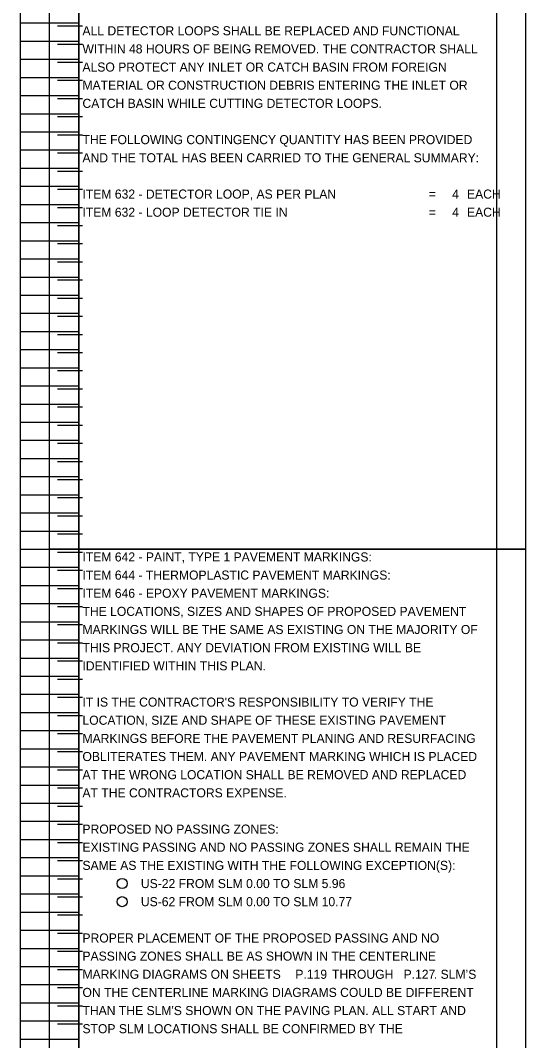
# Model space of a CAD drawing. Extents: x 12522 to 13018, y 1124 to 1902.
# Drawn here: x 12521.92 to 12529.71, y 1701.09 to 1716.83 of the extents above; entities that cross this region are included whole.
import ezdxf

# ---------------------------------------------------------------- set-up
doc = ezdxf.new("R2010")
doc.units = 0
doc.layers.add('SC_Scratch1', color=7, linetype='Continuous')
doc.layers.add('SH_Text', color=7, linetype='Continuous')

msp = doc.modelspace()

# ---------------------------------------------------------------- linework, layer by layer
at = {"layer": 'SC_Scratch1'}
for p, q in [((12521.919, 1708.671), (12521.919, 1728.831)), ((12522.819, 1708.671), (12522.819, 1728.831)), ((12522.819, 1728.831), (12522.819, 1708.671)), ((12521.919, 1716.791), (12522.819, 1716.791)), ((12522.876, 1716.741), (12522.492, 1716.741)), ((12521.919, 1716.511), (12522.819, 1716.511)), ((12522.876, 1716.461), (12522.492, 1716.461)), ((12521.919, 1716.231), (12522.819, 1716.231)), ((12522.876, 1716.181), (12522.492, 1716.181)), ((12521.919, 1715.951), (12522.819, 1715.951)), ((12522.876, 1715.901), (12522.492, 1715.901)), ((12521.919, 1715.671), (12522.819, 1715.671)), ((12522.876, 1715.621), (12522.492, 1715.621)), ((12521.919, 1715.391), (12522.819, 1715.391)), ((12522.876, 1715.341), (12522.492, 1715.341)), ((12521.919, 1715.111), (12522.819, 1715.111)), ((12522.876, 1715.061), (12522.492, 1715.061)), ((12521.919, 1714.831), (12522.819, 1714.831)), ((12522.876, 1714.781), (12522.492, 1714.781)), ((12521.919, 1714.551), (12522.819, 1714.551)), ((12522.876, 1714.501), (12522.492, 1714.501)), ((12521.919, 1714.271), (12522.819, 1714.271)), ((12522.876, 1714.221), (12522.492, 1714.221)), ((12521.919, 1713.991), (12522.819, 1713.991)), ((12522.876, 1713.941), (12522.492, 1713.941)), ((12521.919, 1713.711), (12522.819, 1713.711)), ((12522.876, 1713.661), (12522.492, 1713.661)), ((12521.919, 1713.431), (12522.819, 1713.431)), ((12522.876, 1713.381), (12522.492, 1713.381)), ((12521.919, 1713.151), (12522.819, 1713.151)), ((12522.876, 1713.101), (12522.492, 1713.101)), ((12521.919, 1712.871), (12522.819, 1712.871)), ((12522.876, 1712.821), (12522.492, 1712.821)), ((12521.919, 1712.591), (12522.819, 1712.591)), ((12522.876, 1712.541), (12522.492, 1712.541)), ((12521.919, 1712.311), (12522.819, 1712.311)), ((12522.876, 1712.261), (12522.492, 1712.261)), ((12521.919, 1712.031), (12522.819, 1712.031)), ((12522.876, 1711.981), (12522.492, 1711.981)), ((12521.919, 1711.751), (12522.819, 1711.751)), ((12522.876, 1711.701), (12522.492, 1711.701)), ((12521.919, 1711.471), (12522.819, 1711.471)), ((12522.876, 1711.421), (12522.492, 1711.421)), ((12521.919, 1711.191), (12522.819, 1711.191)), ((12522.876, 1711.141), (12522.492, 1711.141)), ((12521.919, 1710.911), (12522.819, 1710.911)), ((12522.876, 1710.861), (12522.492, 1710.861)), ((12521.919, 1710.631), (12522.819, 1710.631)), ((12522.876, 1710.581), (12522.492, 1710.581)), ((12521.919, 1710.351), (12522.819, 1710.351)), ((12522.876, 1710.301), (12522.492, 1710.301)), ((12521.919, 1710.071), (12522.819, 1710.071)), ((12522.876, 1710.021), (12522.492, 1710.021)), ((12521.919, 1709.791), (12522.819, 1709.791)), ((12522.876, 1709.741), (12522.492, 1709.741)), ((12521.919, 1709.511), (12522.819, 1709.511)), ((12522.876, 1709.461), (12522.492, 1709.461)), ((12521.919, 1709.231), (12522.819, 1709.231)), ((12522.876, 1709.181), (12522.492, 1709.181)), ((12521.919, 1708.951), (12522.819, 1708.951)), ((12522.876, 1708.901), (12522.492, 1708.901)), ((12521.919, 1708.671), (12522.819, 1708.671)), ((12521.919, 1688.511), (12521.919, 1708.671)), ((12521.919, 1708.671), (12522.819, 1708.671)), ((12522.819, 1688.511), (12522.819, 1708.671)), ((12522.819, 1708.671), (12522.819, 1688.511)), ((12522.876, 1708.621), (12522.492, 1708.621)), ((12521.919, 1708.391), (12522.819, 1708.391)), ((12522.876, 1708.341), (12522.492, 1708.341)), ((12521.919, 1708.111), (12522.819, 1708.111)), ((12522.876, 1708.061), (12522.492, 1708.061)), ((12521.919, 1707.831), (12522.819, 1707.831)), ((12522.876, 1707.781), (12522.492, 1707.781)), ((12521.919, 1707.551), (12522.819, 1707.551)), ((12522.876, 1707.501), (12522.492, 1707.501)), ((12521.919, 1707.271), (12522.819, 1707.271)), ((12522.876, 1707.221), (12522.492, 1707.221)), ((12521.919, 1706.991), (12522.819, 1706.991)), ((12522.876, 1706.941), (12522.492, 1706.941)), ((12521.919, 1706.711), (12522.819, 1706.711)), ((12522.876, 1706.661), (12522.492, 1706.661)), ((12521.919, 1706.431), (12522.819, 1706.431)), ((12522.876, 1706.381), (12522.492, 1706.381)), ((12521.919, 1706.151), (12522.819, 1706.151)), ((12522.876, 1706.101), (12522.492, 1706.101)), ((12521.919, 1705.871), (12522.819, 1705.871)), ((12522.876, 1705.821), (12522.492, 1705.821)), ((12521.919, 1705.591), (12522.819, 1705.591)), ((12522.876, 1705.541), (12522.492, 1705.541)), ((12521.919, 1705.311), (12522.819, 1705.311)), ((12522.876, 1705.261), (12522.492, 1705.261)), ((12521.919, 1705.031), (12522.819, 1705.031)), ((12522.876, 1704.981), (12522.492, 1704.981)), ((12521.919, 1704.751), (12522.819, 1704.751)), ((12522.876, 1704.701), (12522.492, 1704.701)), ((12521.919, 1704.471), (12522.819, 1704.471)), ((12522.876, 1704.421), (12522.492, 1704.421)), ((12521.919, 1704.191), (12522.819, 1704.191)), ((12522.876, 1704.141), (12522.492, 1704.141)), ((12521.919, 1703.911), (12522.819, 1703.911)), ((12522.876, 1703.861), (12522.492, 1703.861)), ((12521.919, 1703.631), (12522.819, 1703.631)), ((12522.876, 1703.581), (12522.492, 1703.581)), ((12521.919, 1703.351), (12522.819, 1703.351)), ((12522.876, 1703.301), (12522.492, 1703.301)), ((12521.919, 1703.071), (12522.819, 1703.071)), ((12522.876, 1703.021), (12522.492, 1703.021)), ((12521.919, 1702.791), (12522.819, 1702.791)), ((12522.876, 1702.741), (12522.492, 1702.741)), ((12521.919, 1702.511), (12522.819, 1702.511)), ((12522.876, 1702.461), (12522.492, 1702.461)), ((12521.919, 1702.231), (12522.819, 1702.231)), ((12522.876, 1702.181), (12522.492, 1702.181)), ((12521.919, 1701.951), (12522.819, 1701.951)), ((12522.876, 1701.901), (12522.492, 1701.901)), ((12521.919, 1701.671), (12522.819, 1701.671)), ((12522.876, 1701.621), (12522.492, 1701.621)), ((12521.919, 1701.391), (12522.819, 1701.391)), ((12522.876, 1701.341), (12522.492, 1701.341)), ((12521.919, 1701.111), (12522.819, 1701.111))]:
    msp.add_line(p, q, dxfattribs=at)
for points in [[(12522.369, 1728.831), (12529.709, 1728.831), (12529.709, 1708.671), (12522.369, 1708.671)], [(12522.819, 1728.831), (12529.259, 1728.831), (12529.259, 1708.671), (12522.819, 1708.671)], [(12522.369, 1708.671), (12529.709, 1708.671), (12529.709, 1688.511), (12522.369, 1688.511)], [(12522.819, 1708.671), (12529.259, 1708.671), (12529.259, 1688.511), (12522.819, 1688.511)]]:
    msp.add_lwpolyline(points, close=True, dxfattribs=at)
at = {"layer": 'SH_Text'}
for centre in [(12523.489, 1703.511), (12523.489, 1703.231)]:
    msp.add_circle(centre, 0.0775, dxfattribs=at)

# ---------------------------------------------------------------- texts
for s, p in [('ALL DETECTOR LOOPS SHALL BE REPLACED AND FUNCTIONAL ', (12522.876, 1716.601)), ('WITHIN 48 HOURS OF BEING REMOVED. THE CONTRACTOR SHALL ', (12522.876, 1716.321)), ('ALSO PROTECT ANY INLET OR CATCH BASIN FROM FOREIGN ', (12522.876, 1716.041)), ('MATERIAL OR CONSTRUCTION DEBRIS ENTERING THE INLET OR ', (12522.876, 1715.761)), ('CATCH BASIN WHILE CUTTING DETECTOR LOOPS.', (12522.876, 1715.481)), ('THE FOLLOWING CONTINGENCY QUANTITY HAS BEEN PROVIDED ', (12522.876, 1714.921)), ('AND THE TOTAL HAS BEEN CARRIED TO THE GENERAL SUMMARY:', (12522.876, 1714.641)), ('ITEM 632 - DETECTOR LOOP, AS PER PLAN', (12522.876, 1714.081)), (' =', (12528.164, 1714.081)), ('4', (12528.578, 1714.081)), ('EACH', (12528.806, 1714.081)), ('ITEM 632 - LOOP DETECTOR TIE IN', (12522.876, 1713.801)), (' =', (12528.164, 1713.801)), ('4', (12528.578, 1713.801)), ('EACH', (12528.806, 1713.801)), ('ITEM 642 - PAINT, TYPE 1 PAVEMENT MARKINGS:', (12522.876, 1708.481)), ('ITEM 644 - THERMOPLASTIC PAVEMENT MARKINGS:', (12522.876, 1708.201)), ('ITEM 646 - EPOXY PAVEMENT MARKINGS:', (12522.876, 1707.921)), ('THE LOCATIONS, SIZES AND SHAPES OF PROPOSED PAVEMENT ', (12522.876, 1707.641)), ('MARKINGS WILL BE THE SAME AS EXISTING ON THE MAJORITY OF ', (12522.876, 1707.361)), ('THIS PROJECT. ANY DEVIATION FROM EXISTING WILL BE ', (12522.876, 1707.081)), ('IDENTIFIED WITHIN THIS PLAN. ', (12522.876, 1706.801)), ("IT IS THE CONTRACTOR'S RESPONSIBILITY TO VERIFY THE ", (12522.876, 1706.241)), ('LOCATION, SIZE AND SHAPE OF THESE EXISTING PAVEMENT ', (12522.876, 1705.961)), ('MARKINGS BEFORE THE PAVEMENT PLANING AND RESURFACING ', (12522.876, 1705.681)), ('OBLITERATES THEM. ANY PAVEMENT MARKING WHICH IS PLACED ', (12522.876, 1705.401)), ('AT THE WRONG LOCATION SHALL BE REMOVED AND REPLACED ', (12522.876, 1705.121)), ('AT THE CONTRACTORS EXPENSE.', (12522.876, 1704.841)), ('PROPOSED NO PASSING ZONES:', (12522.876, 1704.281)), ('EXISTING PASSING AND NO PASSING ZONES SHALL REMAIN THE ', (12522.876, 1704.001)), ('SAME AS THE EXISTING WITH THE FOLLOWING EXCEPTION(S):', (12522.876, 1703.721)), ('US-22 FROM SLM 0.00 TO SLM 5.96', (12523.777, 1703.441)), ('US-62 FROM SLM 0.00 TO SLM 10.77', (12523.777, 1703.161)), ('PROPER PLACEMENT OF THE PROPOSED PASSING AND NO ', (12522.876, 1702.601)), ('PASSING ZONES SHALL BE AS SHOWN IN THE CENTERLINE ', (12522.876, 1702.321)), ('MARKING DIAGRAMS ON SHEETS ', (12522.876, 1702.041)), ('P.119', (12526.159, 1702.041)), ('THROUGH            . SLM’S ', (12526.724, 1702.041)), ('P.127', (12527.828, 1702.041)), ('ON THE CENTERLINE MARKING DIAGRAMS COULD BE DIFFERENT ', (12522.876, 1701.761)), ("THAN THE SLM'S SHOWN ON THE PAVING PLAN. ALL START AND ", (12522.876, 1701.481)), ('STOP SLM LOCATIONS SHALL BE CONFIRMED BY THE ', (12522.876, 1701.201))]:
    msp.add_text(s, height=0.14, dxfattribs=at).set_placement(p)

doc.saveas('drawing.dxf')
